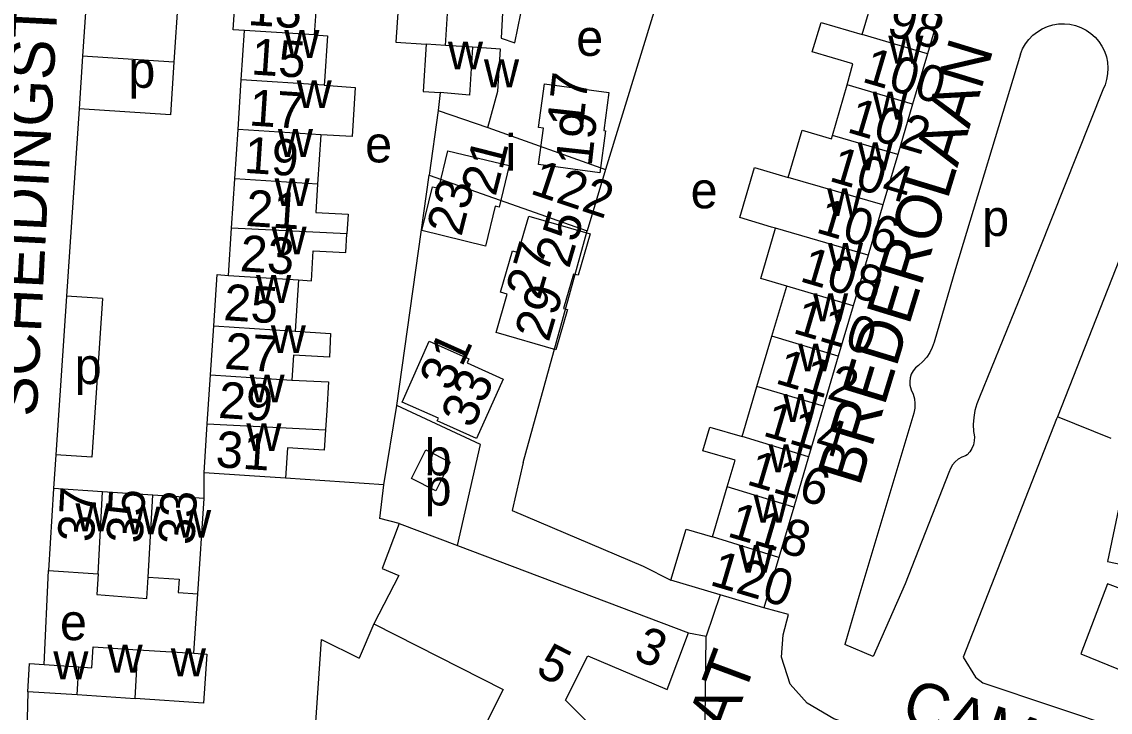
# Model space of a CAD drawing. Extents: x 159700 to 161346, y 381730 to 382922.
# Drawn here: x 160528.5 to 160648.4, y 382017.6 to 382093.7 of the extents above; entities that cross this region are included whole.
import ezdxf

# ---------------------------------------------------------------- set-up
doc = ezdxf.new("R2010")
doc.units = 0
for name, color, linetype in [('BLT_Basislijn', 7, 'Continuous'), ('BLT_Bebouwing', 7, 'Continuous'), ('BLT_Centroide', 7, 'Continuous'), ('BLT_Huisnummer', 7, 'Continuous'), ('BLT_Huisnummer_ tussenligend', 7, 'Continuous'), ('BLT_Huisnummer_reeks', 7, 'Continuous'), ('BLT_Huisnummer_zonder_bebouwing', 7, 'Continuous'), ('BLT_Onderverdeling_panden', 7, 'Continuous'), ('BLT_Plantopo', 7, 'Continuous'), ('BLT_Straatnaam', 7, 'Continuous')]:
    doc.layers.add(name, color=color, linetype=linetype)

msp = doc.modelspace()

# ---------------------------------------------------------------- linework, layer by layer
at = {"layer": 'BLT_Basislijn'}
for p, q in [((160536.8, 382114.41), (160535.16, 382089.9)), ((160546.87, 382113.74), (160545.23, 382089.23)), ((160660.75, 382096.55), (160642.54, 382050.16)), ((160535.16, 382089.9), (160534.78, 382084.11)), ((160545.23, 382089.23), (160535.16, 382089.9)), ((160638.46, 382090.13), (160631.32, 382066.48)), ((160545.23, 382089.23), (160544.85, 382083.44)), ((160647.53, 382086.2), (160639.09, 382064.96)), ((160534.78, 382084.11), (160533.4, 382063.46)), ((160544.85, 382083.44), (160534.78, 382084.11)), ((160569.8, 382051.42), (160573.36, 382076.81)), ((160583.68, 382045.12), (160590.74, 382070.66)), ((160631.32, 382066.48), (160628.96, 382058.4)), ((160639.09, 382064.96), (160633.94, 382052.31)), ((160533.4, 382063.46), (160532.23, 382045.97)), ((160537.36, 382063.2), (160533.4, 382063.46)), ((160537.36, 382063.2), (160536.19, 382045.7)), ((160568.34, 382042.68), (160569.8, 382051.42)), ((160626.71, 382050.58), (160620.67, 382030.37)), ((160648.45, 382047.77), (160642.54, 382050.16)), ((160532.23, 382045.97), (160531.98, 382042.26)), ((160536.19, 382045.7), (160532.23, 382045.97)), ((160548.55, 382041.17), (160548.56, 382043.98)), ((160568.34, 382042.68), (160557.51, 382043.39)), ((160630.59, 382044.02), (160625.76, 382031.74)), ((160530.94, 382022.86), (160531.4, 382033.23)), ((160625.76, 382031.74), (160622.26, 382023.74)), ((160547.43, 382024.1), (160547.86, 382030.65)), ((160605.38, 382030.55), (160603.84, 382025.99)), ((160620.67, 382030.37), (160619.14, 382025.08)), ((160567.26, 382027.36), (160565.63, 382023.58)), ((160601.9, 382026.36), (160603.84, 382025.99)), ((160560.55, 382011.82), (160561.47, 382025.64)), ((160561.47, 382025.64), (160565.63, 382023.58)), ((160622.26, 382023.74), (160619.14, 382025.08))]:
    msp.add_line(p, q, dxfattribs=at)
for points in [[(160596.66, 382095.83), (160598.24, 382095.24), (160592.76, 382077.43)], [(160638.46, 382090.13), (160638.7, 382090.72), (160639.01, 382091.26), (160639.39, 382091.76), (160639.83, 382092.21), (160640.33, 382092.6), (160640.87, 382092.93), (160641.44, 382093.18), (160642.05, 382093.36), (160642.67, 382093.46), (160643.3, 382093.48), (160643.92, 382093.42), (160644.54, 382093.28), (160645.13, 382093.07), (160645.69, 382092.78), (160646.21, 382092.42), (160646.68, 382092), (160647.09, 382091.53), (160647.44, 382091), (160647.72, 382090.44), (160647.93, 382089.84), (160648.05, 382089.23), (160648.1, 382088.6), (160648.07, 382087.97), (160647.96, 382087.35), (160647.78, 382086.75), (160647.53, 382086.2)], [(160628.96, 382058.4), (160628.76, 382057.81), (160628.48, 382057.25), (160628.14, 382056.74), (160627.73, 382056.27), (160627.23, 382055.83)], [(160627.23, 382055.83), (160626.91, 382055.56), (160626.64, 382055.24), (160626.44, 382054.87), (160626.32, 382054.47), (160626.27, 382054.05), (160626.3, 382053.64), (160626.44, 382053.15)], [(160626.44, 382053.15), (160626.65, 382052.67), (160626.79, 382052.16), (160626.84, 382051.64), (160626.82, 382051.11), (160626.71, 382050.58)], [(160576.46, 382035.99), (160579.01, 382047.12), (160569.8, 382051.42)], [(160633.94, 382052.31), (160633.66, 382051.59), (160633.45, 382050.85), (160633.32, 382050.09), (160633.27, 382049.32), (160633.3, 382048.55), (160633.32, 382048.37)], [(160642.54, 382050.16), (160642.45, 382049.95), (160632.17, 382023.66), (160633.53, 382021.46), (160634.31, 382020.85), (160657.35, 382013.14)], [(160633.32, 382048.37), (160633.39, 382047.94), (160633.38, 382047.51), (160633.29, 382047.08), (160633.12, 382046.67), (160632.88, 382046.3), (160632.58, 382045.99), (160632.42, 382045.86)], [(160632.42, 382045.86), (160632, 382045.71), (160631.61, 382045.49), (160631.26, 382045.2), (160630.97, 382044.86), (160630.75, 382044.47), (160630.59, 382044.02)], [(160583.68, 382045.12), (160582.47, 382039.84), (160596.91, 382033.69), (160599.97, 382032.15)], [(160570.04, 382038.42), (160567.92, 382038.97), (160568.34, 382042.68)], [(160636.62, 382010.62), (160617.91, 382016.89), (160614.96, 382018.61), (160613.11, 382020.7), (160612.16, 382023.68), (160612.33, 382026.15), (160612.91, 382028.38), (160610.21, 382029.12)], [(160587.53, 381987.15), (160591.79, 381997.56), (160593.7, 382001.28), (160598.94, 382007.73), (160603.71, 382013.72), (160603.84, 382025.99)], [(160529.14, 382019.87), (160529.05, 382016.87), (160528.74, 382014.45)]]:
    msp.add_lwpolyline(points, dxfattribs=at)
at = {"layer": 'BLT_Bebouwing'}
for p, q in [((160575.14, 382091.07), (160575.62, 382098.75)), ((160561.01, 382097.22), (160560.68, 382092.24)), ((160621.03, 382092.28), (160622.66, 382097.82)), ((160552.65, 382087.29), (160553.01, 382092.74)), ((160628.23, 382090.15), (160626.59, 382084.61)), ((160552.29, 382081.84), (160552.65, 382087.29)), ((160617.76, 382081.18), (160619.39, 382086.73)), ((160574.57, 382085.89), (160574.35, 382083.92)), ((160574.35, 382083.92), (160573.36, 382076.81)), ((160626.59, 382084.61), (160624.95, 382079.06)), ((160551.94, 382076.4), (160552.29, 382081.84)), ((160579.79, 382082.03), (160592.76, 382077.43)), ((160561.42, 382081.25), (160561.06, 382075.8)), ((160624.95, 382079.06), (160623.32, 382073.51)), ((160573.36, 382076.81), (160590.74, 382070.66)), ((160592.76, 382077.43), (160590.74, 382070.66)), ((160551.58, 382070.95), (160551.94, 382076.4)), ((160623.32, 382073.51), (160621.68, 382067.96)), ((160551.24, 382065.75), (160551.58, 382070.95)), ((160621.68, 382067.96), (160620.04, 382062.41)), ((160558.94, 382065.24), (160558.57, 382059.6)), ((160611.09, 382059.04), (160612.73, 382064.57)), ((160620.04, 382062.41), (160618.4, 382056.86)), ((160549.27, 382054.78), (160549.62, 382060.18)), ((160609.45, 382053.52), (160611.09, 382059.04)), ((160618.4, 382056.86), (160616.76, 382051.32)), ((160548.91, 382049.38), (160549.27, 382054.78)), ((160607.81, 382047.99), (160609.45, 382053.52)), ((160616.76, 382051.32), (160615.12, 382045.77)), ((160548.56, 382043.98), (160548.91, 382049.38)), ((160615.12, 382045.77), (160613.49, 382040.22)), ((160531.98, 382042.26), (160531.4, 382033.23)), ((160537.37, 382041.91), (160531.98, 382042.26)), ((160542.9, 382041.54), (160537.37, 382041.91)), ((160604.54, 382036.94), (160606.18, 382042.46)), ((160548.55, 382041.17), (160542.9, 382041.54)), ((160547.86, 382030.65), (160548.55, 382041.17)), ((160613.49, 382040.22), (160611.85, 382034.67)), ((160570.04, 382038.42), (160576.46, 382035.99)), ((160576.46, 382035.99), (160601.9, 382026.36)), ((160611.85, 382034.67), (160610.21, 382029.12)), ((160531.4, 382033.23), (160536.87, 382032.87)), ((160605.38, 382030.55), (160599.97, 382032.15)), ((160610.21, 382029.12), (160605.38, 382030.55)), ((160645.11, 382024.03), (160659.74, 382018.09))]:
    msp.add_line(p, q, dxfattribs=at)
for points in [[(160582.26, 382110.69), (160581.26, 382091.9), (160582.79, 382091.39), (160583.76, 382096.25), (160588.6, 382094.66), (160589.77, 382098.1)], [(160575.62, 382098.75), (160572, 382098.98), (160571.76, 382095.11), (160569.93, 382095.23), (160569.69, 382091.45), (160573.01, 382091.24)], [(160553.01, 382092.74), (160551.75, 382092.82), (160552.07, 382097.8)], [(160622.66, 382097.82), (160629.86, 382095.69), (160628.23, 382090.15)], [(160619.39, 382086.73), (160619.99, 382089.08), (160615.52, 382090.4), (160616.51, 382093.6), (160621.03, 382092.28)], [(160560.68, 382092.24), (160562.13, 382092.14), (160561.8, 382087.15), (160561.77, 382086.7)], [(160573.01, 382091.24), (160572.69, 382086.01), (160574.57, 382085.89)], [(160578.11, 382090.88), (160575.14, 382091.07)], [(160579.79, 382082.03), (160580.9, 382086.06), (160581.2, 382090.69), (160578.11, 382090.88)], [(160561.77, 382086.7), (160565.2, 382086.45), (160564.85, 382081.07), (160561.42, 382081.25)], [(160612.9, 382076.54), (160614.44, 382081.75), (160617.64, 382080.8), (160617.76, 382081.18)], [(160611.5, 382070.94), (160611.04, 382071.08), (160607.55, 382072.11), (160609.18, 382077.64), (160612.9, 382076.54)], [(160561.06, 382075.8), (160560.86, 382072.69), (160564.43, 382072.5), (160564.29, 382070.33)], [(160612.73, 382064.57), (160609.86, 382065.42), (160611.5, 382070.94)], [(160558.94, 382065.24), (160560.37, 382065.15), (160560.58, 382068.45), (160564.15, 382068.26), (160564.29, 382070.33)], [(160549.62, 382060.18), (160549.99, 382065.83), (160551.24, 382065.75)], [(160558.57, 382059.6), (160562.48, 382059.34), (160562.36, 382056.73), (160558.4, 382056.97), (160558.22, 382054.19)], [(160558.22, 382054.19), (160562.24, 382054), (160562.06, 382050.86), (160561.92, 382048.73)], [(160606.18, 382042.46), (160607.04, 382045.39), (160603.49, 382046.43), (160604.26, 382049.04), (160607.81, 382047.99)], [(160561.92, 382048.73), (160561.78, 382046.49), (160557.73, 382046.76), (160557.51, 382043.39)], [(160557.51, 382043.39), (160553.55, 382043.65), (160548.56, 382043.98)], [(160672.62, 382028.67), (160667.2, 382030.8), (160664.98, 382025.12), (160652.03, 382030.19), (160653.21, 382033.2), (160653.95, 382033.05), (160654.67, 382036.53), (160653.85, 382036.7), (160654.49, 382039.81), (160659.76, 382037.62), (160660.84, 382040.24), (160655.08, 382042.63), (160654.92, 382042.66), (160650.02, 382043.67), (160648.07, 382034.22), (160650.52, 382033.71), (160649.53, 382031.19), (160648.07, 382031.76), (160645.11, 382024.03)], [(160570.04, 382038.42), (160568.16, 382033.45), (160569.99, 382032.68)], [(160599.97, 382032.15), (160601.64, 382037.79), (160604.54, 382036.94)], [(160536.87, 382032.87), (160536.74, 382030.57), (160542.26, 382030.15), (160542.39, 382032.51)], [(160542.39, 382032.51), (160545.8, 382032.28), (160545.7, 382030.79), (160547.86, 382030.65)], [(160569.99, 382032.68), (160567.26, 382027.36)], [(160567.26, 382027.36), (160581.5, 382020.11), (160577.96, 382013.12), (160575.23, 382014.5), (160572.3, 382008.73), (160575.02, 382007.35), (160572.09, 382001.58), (160577.96, 381998.58)], [(160590.82, 382023.83), (160599.55, 382020.12), (160601.9, 382026.36)], [(160534.76, 382022.6), (160536.18, 382022.5), (160536.33, 382024.82), (160541.25, 382024.5)], [(160547.43, 382024.1), (160548.86, 382024), (160548.5, 382018.61), (160540.95, 382019.11)], [(160541.25, 382024.5), (160547.43, 382024.1)], [(160588.37, 382018.94), (160590.82, 382023.83)], [(160529.14, 382019.87), (160529.32, 382022.97), (160530.94, 382022.86)], [(160530.94, 382022.86), (160534.76, 382022.6)], [(160534.59, 382019.52), (160529.14, 382019.87)], [(160540.95, 382019.1), (160534.59, 382019.52)], [(160577.96, 381998.58), (160577.55, 381997.5), (160585.71, 381994.82), (160589.02, 382004.99), (160595.64, 382011.62), (160588.37, 382018.94)]]:
    msp.add_lwpolyline(points, dxfattribs=at)
msp.add_lwpolyline([(160572.97, 382046.52), (160575.65, 382045.18), (160574.06, 382042), (160571.4, 382043.38)], close=True, dxfattribs=at)
at = {"layer": 'BLT_Onderverdeling_panden'}
for p, q in [((160560.68, 382092.24), (160553.01, 382092.74)), ((160628.23, 382090.15), (160621.03, 382092.28)), ((160575.14, 382091.07), (160573.01, 382091.24)), ((160561.77, 382086.7), (160552.65, 382087.29)), ((160626.59, 382084.61), (160619.39, 382086.73)), ((160574.35, 382083.92), (160579.79, 382082.03)), ((160561.42, 382081.25), (160552.29, 382081.84)), ((160624.95, 382079.06), (160617.76, 382081.18)), ((160561.06, 382075.8), (160551.94, 382076.4)), ((160623.32, 382073.51), (160612.9, 382076.54)), ((160564.29, 382070.33), (160551.58, 382070.95)), ((160621.68, 382067.96), (160611.5, 382070.94)), ((160551.24, 382065.75), (160558.94, 382065.24)), ((160620.04, 382062.41), (160612.73, 382064.57)), ((160549.62, 382060.18), (160558.57, 382059.6)), ((160618.4, 382056.86), (160611.09, 382059.04)), ((160549.27, 382054.78), (160558.22, 382054.19)), ((160616.76, 382051.32), (160609.45, 382053.52)), ((160548.91, 382049.38), (160561.92, 382048.73)), ((160615.12, 382045.77), (160607.81, 382047.99)), ((160536.87, 382032.87), (160537.37, 382041.91)), ((160613.49, 382040.22), (160606.18, 382042.46)), ((160542.39, 382032.51), (160542.9, 382041.54)), ((160611.85, 382034.67), (160604.54, 382036.94)), ((160540.95, 382019.11), (160541.25, 382024.5)), ((160534.59, 382019.52), (160534.76, 382022.6))]:
    msp.add_line(p, q, dxfattribs=at)
msp.add_lwpolyline([(160578.11, 382090.88), (160577.8, 382085.62), (160574.57, 382085.89)], dxfattribs=at)
at = {"layer": 'BLT_Plantopo'}
for points in [[(160586.05, 382086.85), (160593.15, 382085.9), (160592.58, 382081.71), (160592.76, 382081.68), (160592.13, 382077.06), (160585.39, 382077.97), (160585.93, 382081.97), (160585.4, 382082.04)], [(160584.33, 382072.29), (160591.07, 382070.33), (160589.74, 382065.76), (160589.24, 382065.9), (160588.13, 382062.11), (160588.59, 382061.98), (160587.3, 382057.53), (160580.72, 382059.44), (160581.95, 382063.67), (160581.2, 382063.89), (160582.53, 382068.46), (160583.16, 382068.28)], [(160573.36, 382058.51), (160577.73, 382056.57), (160577.52, 382056.1), (160581.49, 382054.32), (160578.57, 382047.77), (160574.22, 382049.71), (160574.36, 382050.01), (160570.37, 382051.79)]]:
    msp.add_lwpolyline(points, close=True, dxfattribs=at)
msp.add_lwpolyline([(160575.41, 382079.48), (160582.16, 382077.84), (160581.05, 382073.26), (160580.63, 382073.36), (160579.56, 382068.97), (160572.52, 382070.68), (160573.7, 382075.52), (160574.41, 382075.35), (160575.41, 382079.47)], dxfattribs=at)

# ---------------------------------------------------------------- texts
at = {"layer": 'BLT_Centroide'}
for s, p in [('w', (160557.39, 382089.72)), ('e', (160589.54, 382089.94)), ('w', (160623.91, 382089.09)), ('w', (160575.41, 382088.44)), ('p', (160540.21, 382086.42)), ('w', (160579.38, 382086.47)), ('w', (160558.75, 382084.19)), ('w', (160622.17, 382082.91)), ('w', (160556.68, 382078.81)), ('i', (160581.74, 382077.28)), ('e', (160566.29, 382078.2)), ('w', (160620.54, 382077.34)), ('w', (160556.32, 382073.38)), ('e', (160602.14, 382073.14)), ('w', (160617.17, 382072.28)), ('p', (160634.25, 382070.09)), ('w', (160555.98, 382068.06)), ('w', (160617.26, 382066.25)), ('w', (160554.28, 382062.72)), ('w', (160615.62, 382060.69)), ('w', (160555.9, 382057.19)), ('w', (160613.98, 382055.16)), ('p', (160534.3, 382053.77)), ('w', (160553.56, 382051.75)), ('w', (160612.34, 382049.59)), ('w', (160553.21, 382046.38)), ('b', (160572.84, 382043.71)), ('w', (160610.71, 382044.06)), ('p', (160572.84, 382040.39)), ('w', (160534.39, 382037.56)), ('w', (160609.07, 382038.5)), ('w', (160539.89, 382037.2)), ('w', (160545.47, 382036.84)), ('w', (160607.43, 382032.97)), ('e', (160532.68, 382025.55)), ('w', (160537.92, 382021.97)), ('w', (160531.95, 382021.25)), ('w', (160544.89, 382021.56))]:
    msp.add_text(s, height=4, dxfattribs=at).set_placement(p)
at = {"layer": 'BLT_Huisnummer'}
for s, rotation, p in [('98', 343.5545, (160623.58, 382092.28)), ('15', 356.2664, (160553.67, 382087.9)), ('102', 343.5523, (160619.23, 382081.57)), ('19', 356.2622, (160552.9, 382077.06)), ('122', 341.5488, (160584.33, 382074.8)), ('106', 343.5523, (160615.81, 382070.52)), ('23', 356.2618, (160552.43, 382066.22)), ('110', 343.548, (160613.27, 382059.44)), ('27', 356.2671, (160550.72, 382055.46)), ('114', 343.5531, (160609.96, 382048.13)), ('31', 356.2621, (160549.76, 382044.63)), ('37', 86.7942, (160536.41, 382036.3)), ('33', 86.8022, (160547.47, 382035.99)), ('120', 343.5488, (160604.11, 382031.67))]:
    msp.add_text(s, height=4, rotation=rotation, dxfattribs=at).set_placement(p)
at = {"layer": 'BLT_Huisnummer_ tussenligend'}
for s, rotation, p in [('13', 356.2664, (160553.3, 382093.35)), ('100', 343.5545, (160620.89, 382087.12)), ('17', 356.2664, (160553.43, 382082.28)), ('104', 343.5523, (160617.26, 382076.2)), ('21', 356.2622, (160553.06, 382071.21)), ('108', 343.5523, (160614.03, 382065.14)), ('25', 356.2618, (160550.63, 382060.83)), ('112', 343.548, (160611.33, 382053.9)), ('29', 356.2671, (160550.05, 382050.06)), ('116', 343.5531, (160608.17, 382042.75)), ('35', 86.8022, (160541.77, 382036.16)), ('118', 343.551, (160606.04, 382037.02))]:
    msp.add_text(s, height=4, rotation=rotation, dxfattribs=at).set_placement(p)
at = {"layer": 'BLT_Huisnummer_reeks'}
for s, rotation, p in [('3', 337.2626, (160595.68, 382023.55)), ('5', 333.0678, (160584.93, 382021.83))]:
    msp.add_text(s, height=4, rotation=rotation, dxfattribs=at).set_placement(p)
at = {"layer": 'BLT_Huisnummer_zonder_bebouwing'}
for s, rotation, p in [('17', 83.7396, (160590.28, 382081.93)), ('19', 83.7396, (160591.23, 382077.67)), ('21', 75.7396, (160580.65, 382074.36)), ('23', 75.7396, (160576.88, 382069.94)), ('25', 73.7396, (160588.75, 382066.41)), ('27', 73.7396, (160585.52, 382062.93)), ('29', 73.7396, (160586.5, 382058.3)), ('31', 65.7396, (160575.74, 382052.84)), ('33', 65.7396, (160578.12, 382048.76))]:
    msp.add_text(s, height=4, rotation=rotation, dxfattribs=at).set_placement(p)
at = {"layer": 'BLT_Straatnaam'}
for s, height, rotation, p in [('SCHEIDINGSTRAAT', 4.9999, 87.1045, (160530.11, 382050.11)), ('BREDEROLAAN', 5, 73.0238, (160620.77, 382042.37)), ('CAMPHUYSENSTRAAT', 5, 69.5327, (160583.69, 381954.24)), ('CAMPHUYSENSTRAAT', 5, 341.4268, (160625.12, 382016.68))]:
    msp.add_text(s, height=height, rotation=rotation, dxfattribs=at).set_placement(p)

doc.saveas('drawing.dxf')
